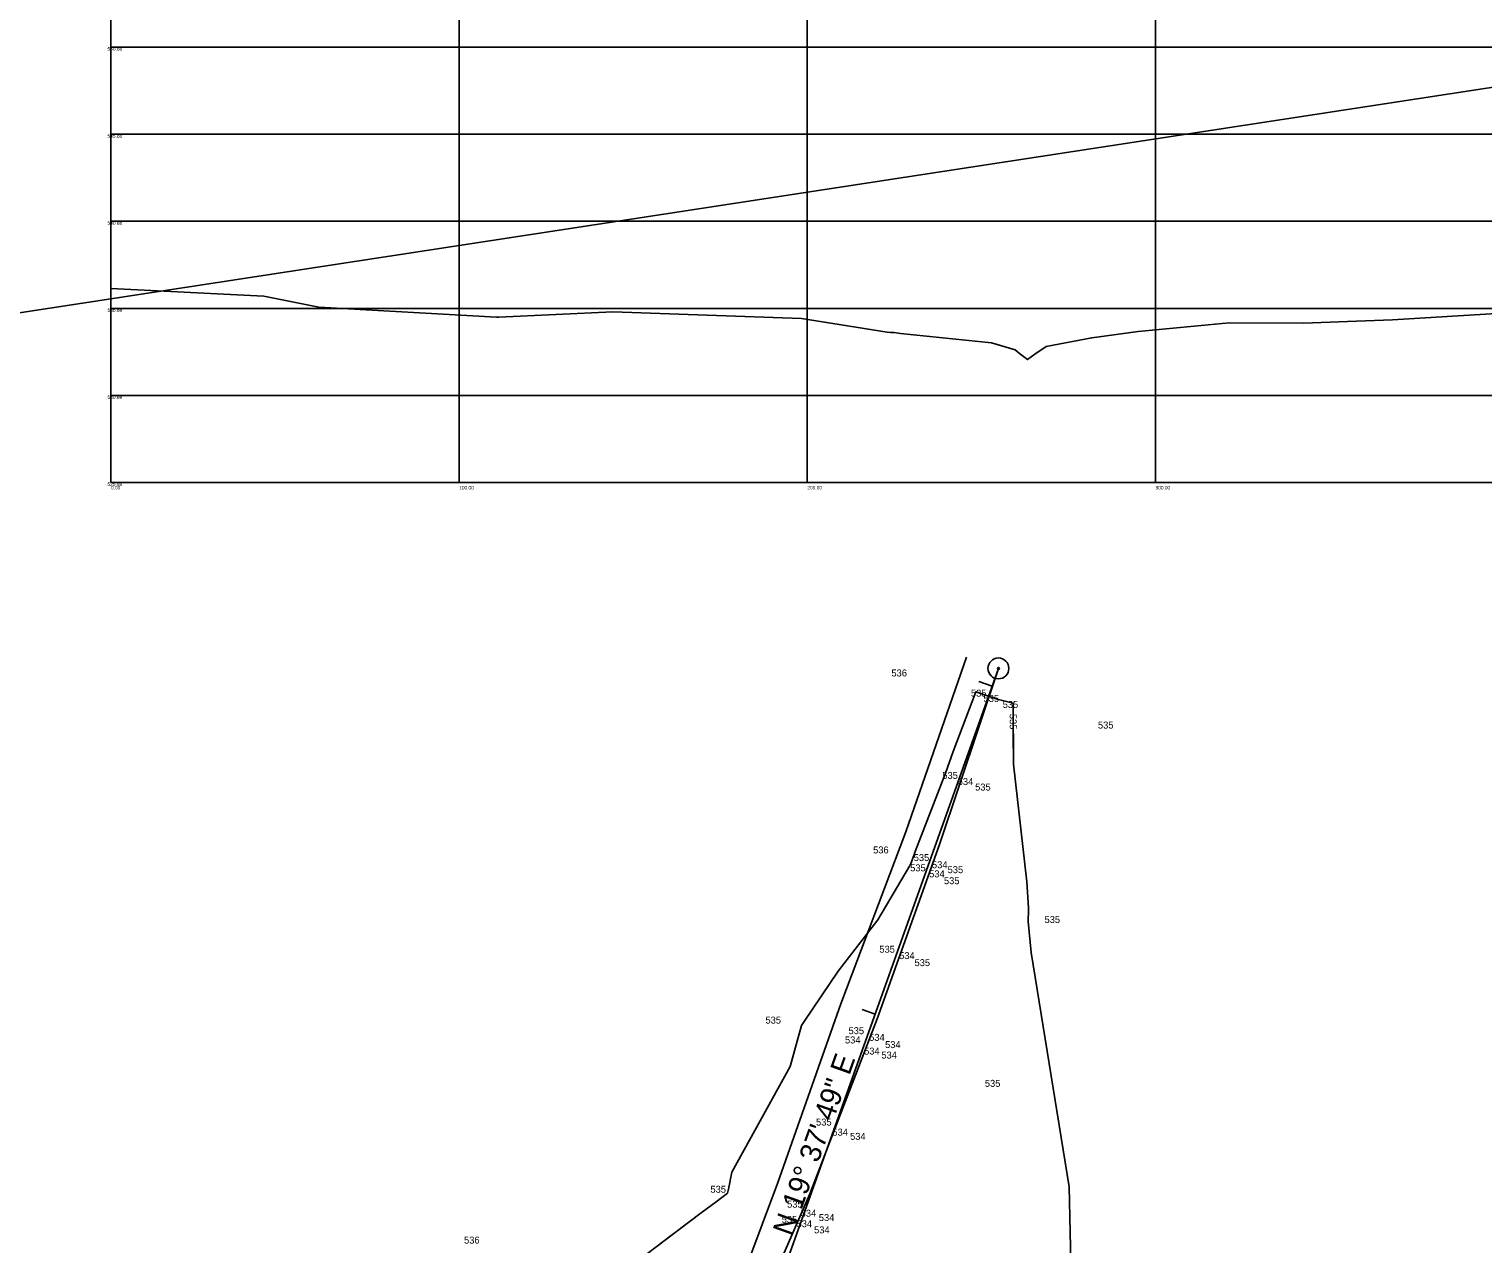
# Model space of a CAD drawing. Extents: x 1787461 to 1970323, y 938412 to 1118748.
# Drawn here: x 1968194.3 to 1968611.9, y 1118052.7 to 1118401.6 of the extents above; entities that cross this region are included whole.
import ezdxf

# ---------------------------------------------------------------- set-up
doc = ezdxf.new("R2010")
doc.units = 0
for name, color, linetype in [('Default', 7, 'Continuous'), ('HHA ADDITIONAL XSs', 7, 'Continuous'), ('Level 1', 7, 'Continuous'), ('RD_EX_H2O', 7, 'Continuous'), ('RD_HC_CL', 7, 'Continuous'), ('RD_HC_Data', 7, 'Continuous'), ('RD_HC_Data_Tic', 7, 'Continuous'), ('RD_SMD_Locator', 7, 'Continuous')]:
    doc.layers.add(name, color=color, linetype=linetype)

msp = doc.modelspace()

# ---------------------------------------------------------------- linework, layer by layer
at = {"layer": 'Default'}
msp.add_lwpolyline([(1968217.84, 1118271.38), (1968217.84, 1118405.41), (1969950.7, 1118405.41), (1969950.7, 1118271.38)], close=True, dxfattribs=at)
for points in [[(1968349.09, 1118032.64), (1968387.31, 1118061.68), (1968391.7, 1118064.82), (1968394.94, 1118067.34), (1968395.16, 1118068.42), (1968396.19, 1118073.35), (1968412.95, 1118103.64), (1968416.17, 1118115.42), (1968416.96, 1118116.59), (1968426.73, 1118131.01), (1968438.06, 1118145.83), (1968447.16, 1118161.16), (1968447.36, 1118161.55), (1968447.42, 1118161.71), (1968447.43, 1118161.73), (1968448.55, 1118164.6), (1968448.85, 1118165.44), (1968457.51, 1118187.91), (1968459.73, 1118194.09), (1968466.27, 1118211.28), (1968472.4, 1118209.19), (1968476.94, 1118207.99), (1968477.02, 1118190.46), (1968480.85, 1118156.66), (1968481.33, 1118149.27), (1968481.37, 1118148.66), (1968481.28, 1118145.33), (1968482.16, 1118136.42), (1968493.04, 1118069.17), (1968493.9, 1118030.09)], [(1968375.54, 1118052.74), (1968387.31, 1118061.68), (1968391.7, 1118064.82), (1968394.94, 1118067.34), (1968395.16, 1118068.42), (1968396.19, 1118073.35), (1968412.95, 1118103.64), (1968416.17, 1118115.42), (1968416.96, 1118116.59), (1968426.73, 1118131.01), (1968438.06, 1118145.83), (1968447.16, 1118161.16), (1968447.36, 1118161.55), (1968447.42, 1118161.71), (1968447.43, 1118161.73), (1968448.55, 1118164.6), (1968448.85, 1118165.44), (1968457.51, 1118187.91), (1968459.73, 1118194.09), (1968466.27, 1118211.28), (1968472.4, 1118209.19), (1968476.94, 1118207.99), (1968476.95, 1118205.36)], [(1968375.54, 1118052.74), (1968387.31, 1118061.68), (1968391.7, 1118064.82), (1968394.94, 1118067.34), (1968395.16, 1118068.42), (1968396.19, 1118073.35), (1968412.95, 1118103.64), (1968416.17, 1118115.42), (1968416.96, 1118116.59), (1968426.73, 1118131.01), (1968438.06, 1118145.83), (1968447.16, 1118161.16), (1968447.36, 1118161.55), (1968447.42, 1118161.71), (1968447.43, 1118161.73), (1968448.55, 1118164.6), (1968448.85, 1118165.44), (1968457.51, 1118187.91), (1968459.73, 1118194.09), (1968466.27, 1118211.28), (1968472.4, 1118209.19), (1968476.94, 1118207.99), (1968476.95, 1118205.36)], [(1968375.54, 1118052.74), (1968387.31, 1118061.68), (1968391.7, 1118064.82), (1968394.94, 1118067.34), (1968395.16, 1118068.42), (1968396.19, 1118073.35), (1968412.95, 1118103.64), (1968416.17, 1118115.42), (1968416.96, 1118116.59), (1968426.73, 1118131.01), (1968438.06, 1118145.83), (1968447.16, 1118161.16), (1968447.36, 1118161.55), (1968447.42, 1118161.71), (1968447.43, 1118161.73), (1968448.55, 1118164.6), (1968448.85, 1118165.44), (1968457.51, 1118187.91), (1968459.73, 1118194.09), (1968466.27, 1118211.28), (1968472.4, 1118209.19), (1968476.94, 1118207.99), (1968476.95, 1118205.36)], [(1968375.54, 1118052.74), (1968387.31, 1118061.68), (1968391.7, 1118064.82), (1968394.94, 1118067.34), (1968395.16, 1118068.42), (1968396.19, 1118073.35), (1968412.95, 1118103.64), (1968416.17, 1118115.42), (1968416.96, 1118116.59), (1968426.73, 1118131.01), (1968438.06, 1118145.83), (1968447.16, 1118161.16), (1968447.36, 1118161.55), (1968447.42, 1118161.71), (1968447.43, 1118161.73), (1968448.55, 1118164.6), (1968448.85, 1118165.44), (1968457.51, 1118187.91), (1968459.73, 1118194.09), (1968466.27, 1118211.28), (1968472.4, 1118209.19), (1968476.94, 1118207.99), (1968476.95, 1118205.36)], [(1968375.54, 1118052.74), (1968387.31, 1118061.68), (1968391.7, 1118064.82), (1968394.94, 1118067.34), (1968395.16, 1118068.42), (1968396.19, 1118073.35), (1968412.95, 1118103.64), (1968416.17, 1118115.42), (1968416.96, 1118116.59), (1968426.73, 1118131.01), (1968438.06, 1118145.83), (1968447.16, 1118161.16), (1968447.36, 1118161.55), (1968447.42, 1118161.71), (1968447.43, 1118161.73), (1968448.55, 1118164.6), (1968448.85, 1118165.44), (1968457.51, 1118187.91), (1968459.73, 1118194.09), (1968466.27, 1118211.28), (1968472.4, 1118209.19), (1968476.94, 1118207.99), (1968476.95, 1118205.36)], [(1968375.54, 1118052.74), (1968387.31, 1118061.68), (1968391.7, 1118064.82), (1968394.94, 1118067.34), (1968395.16, 1118068.42), (1968396.19, 1118073.35), (1968412.95, 1118103.64), (1968416.17, 1118115.42), (1968416.96, 1118116.59), (1968426.73, 1118131.01), (1968438.06, 1118145.83), (1968447.16, 1118161.16), (1968447.36, 1118161.55), (1968447.42, 1118161.71), (1968447.43, 1118161.73), (1968448.55, 1118164.6), (1968448.85, 1118165.44), (1968457.51, 1118187.91), (1968459.73, 1118194.09), (1968466.27, 1118211.28), (1968472.4, 1118209.19), (1968476.94, 1118207.99), (1968476.95, 1118205.36)], [(1968476.98, 1118199.36), (1968477.02, 1118190.46), (1968480.85, 1118156.66), (1968481.33, 1118149.27), (1968481.37, 1118148.66), (1968481.28, 1118145.33), (1968482.16, 1118136.42), (1968493.04, 1118069.17), (1968493.9, 1118030.09), (1968473.08, 1118012.02), (1968471.33, 1118011.05)], [(1968476.98, 1118199.36), (1968477.02, 1118190.46), (1968480.85, 1118156.66), (1968481.33, 1118149.27), (1968481.37, 1118148.66), (1968481.28, 1118145.33), (1968482.16, 1118136.42), (1968493.04, 1118069.17), (1968493.9, 1118030.09), (1968473.08, 1118012.02), (1968471.33, 1118011.05)], [(1968476.98, 1118199.36), (1968477.02, 1118190.46), (1968480.85, 1118156.66), (1968481.33, 1118149.27), (1968481.37, 1118148.66), (1968481.28, 1118145.33), (1968482.16, 1118136.42), (1968493.04, 1118069.17), (1968493.9, 1118030.09), (1968473.08, 1118012.02), (1968471.33, 1118011.05)], [(1968476.98, 1118199.36), (1968477.02, 1118190.46), (1968480.85, 1118156.66), (1968481.33, 1118149.27), (1968481.37, 1118148.66), (1968481.28, 1118145.33), (1968482.16, 1118136.42), (1968493.04, 1118069.17), (1968493.9, 1118030.09), (1968473.08, 1118012.02), (1968471.33, 1118011.05)], [(1968476.98, 1118199.36), (1968477.02, 1118190.46), (1968480.85, 1118156.66), (1968481.33, 1118149.27), (1968481.37, 1118148.66), (1968481.28, 1118145.33), (1968482.16, 1118136.42), (1968493.04, 1118069.17), (1968493.9, 1118030.09), (1968473.08, 1118012.02), (1968471.33, 1118011.05)], [(1968476.98, 1118199.36), (1968477.02, 1118190.46), (1968480.85, 1118156.66), (1968481.33, 1118149.27), (1968481.37, 1118148.66), (1968481.28, 1118145.33), (1968482.16, 1118136.42), (1968493.04, 1118069.17), (1968493.9, 1118030.09), (1968473.08, 1118012.02), (1968471.33, 1118011.05)]]:
    msp.add_lwpolyline(points, dxfattribs=at)
at = {"layer": 'HHA ADDITIONAL XSs'}
msp.add_lwpolyline([(1969084.5, 1118456.85), (1968180.14, 1118318.35), (1967682.43, 1118198.9), (1966417.22, 1117847.18)], dxfattribs=at)
at = {"layer": 'Level 1'}
for p, q in [((1968317.84, 1118271.38), (1968317.84, 1118405.41)), ((1968417.84, 1118271.38), (1968417.84, 1118405.41)), ((1968517.84, 1118271.38), (1968517.84, 1118405.41)), ((1968217.84, 1118396.38), (1969950.7, 1118396.38)), ((1968217.84, 1118371.38), (1969950.7, 1118371.38)), ((1968217.84, 1118346.38), (1969950.7, 1118346.38)), ((1968217.84, 1118321.38), (1969950.7, 1118321.38)), ((1968217.84, 1118296.38), (1969950.7, 1118296.38))]:
    msp.add_line(p, q, dxfattribs=at)
msp.add_lwpolyline([(1968217.84, 1118327.06), (1968261.72, 1118324.92), (1968277.56, 1118321.72), (1968328.6, 1118318.88), (1968329.23, 1118318.84), (1968361.95, 1118320.42), (1968416.15, 1118318.48), (1968440.75, 1118314.53), (1968441.73, 1118314.48), (1968442.77, 1118314.41), (1968444.59, 1118314.19), (1968470.77, 1118311.48), (1968477.57, 1118309.5), (1968478.8, 1118308.45), (1968481.09, 1118306.67), (1968483.15, 1118308.18), (1968486.44, 1118310.42), (1968499.52, 1118312.93), (1968512.9, 1118314.7), (1968539.01, 1118317.22), (1968560.47, 1118317.11), (1968572.98, 1118317.56), (1968585.88, 1118318.04), (1968628.31, 1118320.69)], dxfattribs=at)
at = {"layer": 'RD_EX_H2O'}
for points in [[(1968463.6, 1118221.24), (1968446.15, 1118171.08), (1968427.44, 1118121.66), (1968409.27, 1118070.12), (1968391.69, 1118023.04), (1968369.63, 1117964.38), (1968369.78, 1117956.13)], [(1968472.72, 1118217.99), (1968455.85, 1118167.39), (1968437.87, 1118117.32), (1968418.56, 1118067.13), (1968399.48, 1118023.33), (1968378.92, 1117963.66), (1968377.45, 1117955.88)]]:
    msp.add_lwpolyline(points, dxfattribs=at)
at = {"layer": 'RD_HC_CL'}
msp.add_line((1968370.12, 1117930.34), (1968472.72, 1118217.99), dxfattribs=at)
at = {"layer": 'RD_HC_Data'}
for radius in [3, 0.282]:
    msp.add_circle((1968472.72, 1118217.99), radius, dxfattribs=at)
at = {"layer": 'RD_HC_Data_Tic'}
for p, q in [((1968470.91, 1118212.9), (1968467.14, 1118214.25)), ((1968437.31, 1118118.71), (1968433.55, 1118120.06))]:
    msp.add_line(p, q, dxfattribs=at)
at = {"layer": 'RD_SMD_Locator'}
msp.add_circle((1968472.72, 1118217.99), 0.001, dxfattribs=at)

# ---------------------------------------------------------------- texts
at = {"layer": 'Default'}
for s, p in [('536', (1968442, 1118215.68)), ('535', (1968464.83, 1118209.88)), ('535', (1968468.44, 1118208.37)), ('535', (1968473.95, 1118206.63)), ('535', (1968501.31, 1118200.72)), ('535', (1968456.62, 1118186.27)), ('534', (1968461.04, 1118184.49)), ('535', (1968466.04, 1118182.92)), ('536', (1968436.74, 1118164.86)), ('535', (1968448.4, 1118162.66)), ('535', (1968447.38, 1118159.72)), ('534', (1968453.64, 1118160.61)), ('535', (1968458.14, 1118159.2)), ('534', (1968452.83, 1118157.99)), ('535', (1968457.08, 1118156.03)), ('535', (1968485.97, 1118144.88)), ('535', (1968438.53, 1118136.35)), ('534', (1968444.21, 1118134.52)), ('535', (1968448.63, 1118132.5)), ('535', (1968405.82, 1118116)), ('535', (1968429.67, 1118112.97)), ('534', (1968428.66, 1118110.3)), ('534', (1968435.6, 1118111.05)), ('534', (1968440.18, 1118108.97)), ('534', (1968434.15, 1118107.1)), ('534', (1968439.1, 1118105.96)), ('535', (1968468.83, 1118097.84)), ('535', (1968420.35, 1118086.72)), ('534', (1968425.04, 1118083.82)), ('534', (1968430.12, 1118082.63)), ('535', (1968390.02, 1118067.43)), ('535', (1968412.04, 1118063.14)), ('535', (1968410.49, 1118058.76)), ('534', (1968415.93, 1118060.54)), ('534', (1968421.14, 1118059.3)), ('534', (1968414.75, 1118057.53)), ('534', (1968419.78, 1118055.77)), ('536', (1968319.25, 1118052.83))]:
    msp.add_text(s, height=2, dxfattribs=at).set_placement(p)
msp.add_text('535', height=2, rotation=270.2817, dxfattribs=at).set_placement((1968475.95, 1118204.93))
msp.add_text('535', height=2, rotation=270.2817, dxfattribs=at).set_placement((1968475.95, 1118204.93))
msp.add_text('535', height=2, rotation=270.2817, dxfattribs=at).set_placement((1968475.95, 1118204.93))
msp.add_text('535', height=2, rotation=270.2817, dxfattribs=at).set_placement((1968475.95, 1118204.93))
msp.add_text('535', height=2, rotation=270.2817, dxfattribs=at).set_placement((1968475.95, 1118204.93))
msp.add_text('535', height=2, rotation=270.2817, dxfattribs=at).set_placement((1968475.95, 1118204.93))
at = {"layer": 'Level 1'}
for s, p in [('550.88', (1968216.84, 1118395.38)), ('545.88', (1968216.84, 1118370.38)), ('540.88', (1968216.84, 1118345.38)), ('535.88', (1968216.84, 1118320.38)), ('530.88', (1968216.84, 1118295.38)), ('525.88', (1968216.84, 1118270.38)), ('0.00', (1968217.84, 1118269.38)), ('100.00', (1968317.84, 1118269.38)), ('200.00', (1968417.84, 1118269.38)), ('300.00', (1968517.84, 1118269.38))]:
    msp.add_text(s, height=1, dxfattribs=at).set_placement(p)
at = {"layer": 'RD_HC_Data'}
msp.add_text('N 19%%d 37\' 49" E', height=6, rotation=70.3698, dxfattribs=at).set_placement((1968413.42, 1118054.69))

doc.saveas('drawing.dxf')
